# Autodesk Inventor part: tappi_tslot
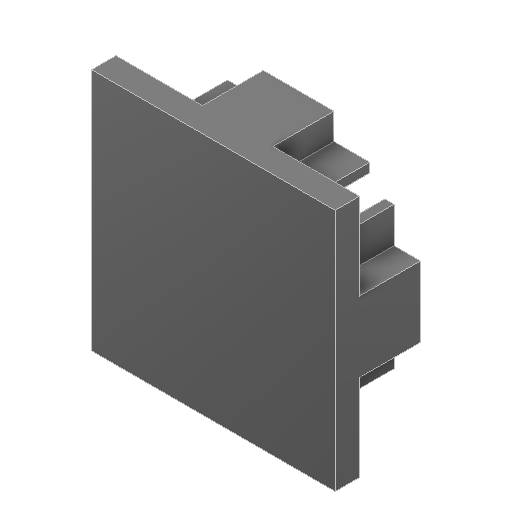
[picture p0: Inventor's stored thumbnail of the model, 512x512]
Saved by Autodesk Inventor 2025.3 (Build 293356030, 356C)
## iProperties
Created: 2025-05
Part Number: tappi_tslot
Material: Plastica ABS
Document SubType Name: Modeling
Designer: R5800u
Density: 1.06 g/cm^3
Appearance: Liscia - Nero
Author: R5800u
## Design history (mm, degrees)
sketch "Schizzo1"
  geometry: L1 (-10, -10)-(10, -10); L2 (10, -10)-(10, 10); L3 (10, 10)-(-10, 10); L4 (-10, 10)-(-10, -10); L5 (-10, -10)-(10, 10); L6 (10, -10)-(-10, 10); 1 further point
  constraints: 12 end point, 2 midpoint, 2 parallel, 1 horizontal, 1 perpendicular
  dimensions: "d0" = 20 distance of L3.end L2.end; "d1" = 20 distance of L2.end L1.end
extrude "Estrusione1" new body sketch "Schizzo1" distance "d2" = 2; taper "d3" = 0 deg
sketch "Schizzo3"
  geometry: L1 (-10, -10)-(-10, 10) reference; L2 (-10, -2.898)-(-7.84, -2.898); L3 (-7.84, -2.898)-(-7.84, -5.843); L4 (-7.84, -5.843)-(-7.082, -5.843); L5 (-7.082, -5.843)-(-4.099, -2.898); L6 (-4.099, -2.898)-(-4.099, 0); L7 (-4.099, 0)-(-10, 0); L8 (-10, -2.898)-(-10, 0); L9 (-10, 2.898)-(-7.84, 2.898); L10 (-7.84, 2.898)-(-7.84, 5.843); L11 (-7.84, 5.843)-(-7.082, 5.843); L12 (-7.082, 5.843)-(-4.099, 2.898); L13 (-4.099, 2.898)-(-4.099, 0); L14 (-10, 2.898)-(-10, 0); L15 (-2.898, 10)-(-2.898, 7.84); L16 (-2.898, 7.84)-(-5.843, 7.84); L17 (-5.843, 7.84)-(-5.843, 7.082); L18 (-5.843, 7.082)-(-2.898, 4.099); L19 (-2.898, 4.099)-(0, 4.099); L20 (0, 4.099)-(0, 10); L21 (-2.898, 10)-(0, 10); L22 (2.898, 10)-(2.898, 7.84); L23 (2.898, 7.84)-(5.843, 7.84); L24 (5.843, 7.84)-(5.843, 7.082); L25 (5.843, 7.082)-(2.898, 4.099); L26 (2.898, 4.099)-(0, 4.099); L27 (2.898, 10)-(0, 10); L28 (10, 2.898)-(7.84, 2.898); L29 (7.84, 2.898)-(7.84, 5.843); L30 (7.84, 5.843)-(7.082, 5.843); L31 (7.082, 5.843)-(4.099, 2.898); L32 (4.099, 2.898)-(4.099, 0); L33 (4.099, 0)-(10, 0); L34 (10, 2.898)-(10, 0); L35 (10, -2.898)-(7.84, -2.898); L36 (7.84, -2.898)-(7.84, -5.843); L37 (7.84, -5.843)-(7.082, -5.843); L38 (7.082, -5.843)-(4.099, -2.898); L39 (4.099, -2.898)-(4.099, 0); L40 (10, -2.898)-(10, 0); L41 (2.898, -10)-(2.898, -7.84); L42 (2.898, -7.84)-(5.843, -7.84); L43 (5.843, -7.84)-(5.843, -7.082); L44 (5.843, -7.082)-(2.898, -4.099); L45 (2.898, -4.099)-(0, -4.099); L46 (0, -4.099)-(0, -10); L47 (2.898, -10)-(0, -10); L48 (-2.898, -10)-(-2.898, -7.84); L49 (-2.898, -7.84)-(-5.843, -7.84); L50 (-5.843, -7.84)-(-5.843, -7.082); L51 (-5.843, -7.082)-(-2.898, -4.099); L52 (-2.898, -4.099)-(0, -4.099); L53 (-2.898, -10)-(0, -10); C1 r 2 at (0, 0); 2 further points
  constraints: 104 end point, 9 point on line, 5 symmetric about line, 2 perpendicular, 1 centre point, 1 coincident, 1 collinear, 1 horizontal, 1 midpoint, 1 parallel, 101 other
  dimensions: "d5" = 4 diameter of C1; "d10" = 360 deg dimension on point (0, 0) L2.start (derived)
extrude "Estrusione2" join sketch "Schizzo3" distance "d6" = 5; taper "d7" = 0 deg
node "Solido1"
node "Schizzo - Serie circolare1" dims "d10" = 360 deg (derived)
